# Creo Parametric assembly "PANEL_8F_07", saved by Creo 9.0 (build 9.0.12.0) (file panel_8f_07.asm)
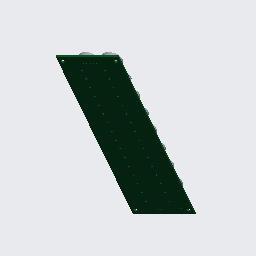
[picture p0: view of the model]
Units: millimeter Newton Second (mmNs); MM, TONNE, SECS

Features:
  1. coordinate system "PANEL_8F_07"
  2. imported feature "Import Feature id 4"
  3. component "PCB_8F"
  4. component "TX_8F_T1"
  5. component "TX_8F_T1"
  6. component "TX_8F_T1"
  7. component "TX_8F_T1"
  8. component "TX_8F_T1"
  9. component "TX_8F_T1"
  10. component "TX_8F_T1"
  11. component "TX_8F_T1"
  12. component "TX_8F_T1"
  13. component "TX_8F_T1"
  14. component "TX_8F_T1"
  15. component "TX_8F_T1"
  16. component "TX_8F_T1"
  17. component "TX_8F_T1"
  18. component "TX_8F_T1"
  19. component "TX_8F_T1"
